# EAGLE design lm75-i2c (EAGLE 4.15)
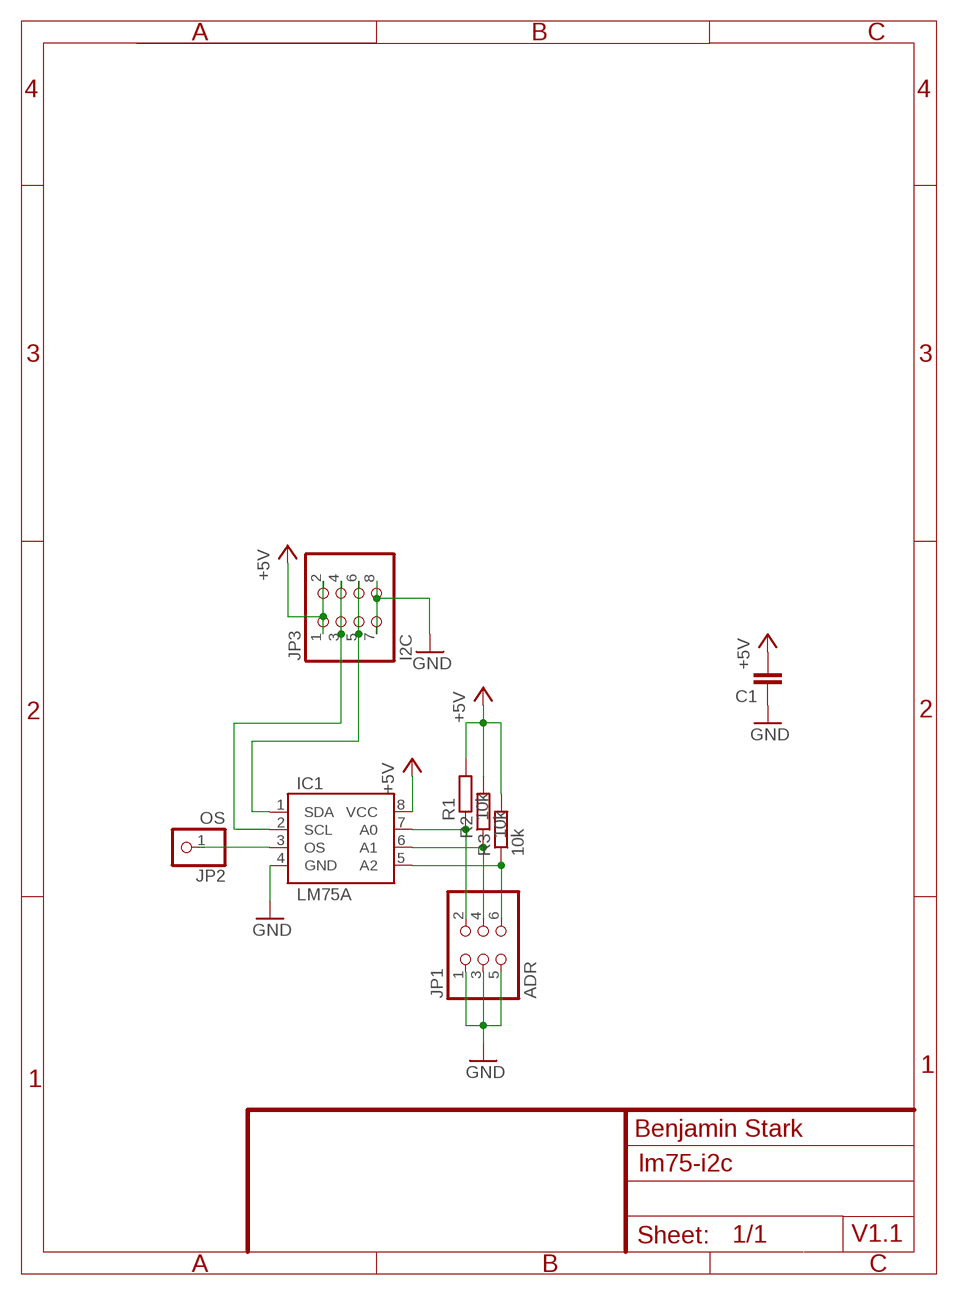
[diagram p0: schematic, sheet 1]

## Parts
C1  C-EU050-024X044  [C050-024X044]
IC1  LM75A  [SO8]
JP1  ADR  PINHD-2X3  [2X03]
JP2  OS  PINHD-1X1  [1X01]
JP3  I2C  PINHD-2X4  [2X04]
R1  10k  R-EU_0207/12  [0207/12]
R2  10k  R-EU_0207/12  [0207/12]
R3  10k  R-EU_0207/12  [0207/12]

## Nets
+5V: C1.2 IC1.8(VCC) JP3.1 JP3.2 R1.2 R2.2 R3.2
GND: C1.1 IC1.4(GND) JP1.1 JP1.3 JP1.5 JP3.7 JP3.8
N$1: IC1.3(OS) JP2.1
N$2: IC1.7(A0) JP1.2 R1.1
N$3: IC1.6(A1) JP1.4 R2.1
N$4: IC1.1(SDA) JP3.5 JP3.6
N$5: IC1.2(SCL) JP3.3 JP3.4
N$6: IC1.5(A2) JP1.6 R3.1

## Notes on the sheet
- Benjamin Stark
- V1.1

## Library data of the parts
C1 = rcl:C-EU: CAPACITOR, European symbol
IC1 = philips-3:LM75A
JP1 = pinhead:PINHD-2X3: PIN HEADER
JP2 = pinhead:PINHD-1X1: PIN HEADER
JP3 = pinhead:PINHD-2X4: PIN HEADER
R1-R3 = rcl:R-EU_: RESISTOR, European symbol

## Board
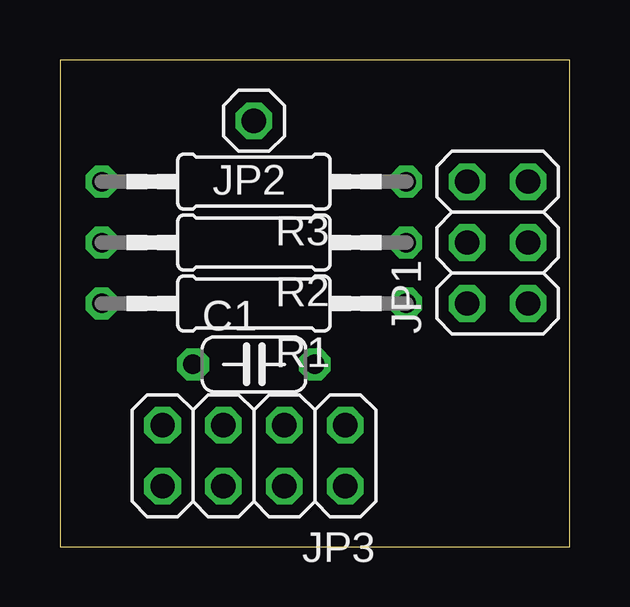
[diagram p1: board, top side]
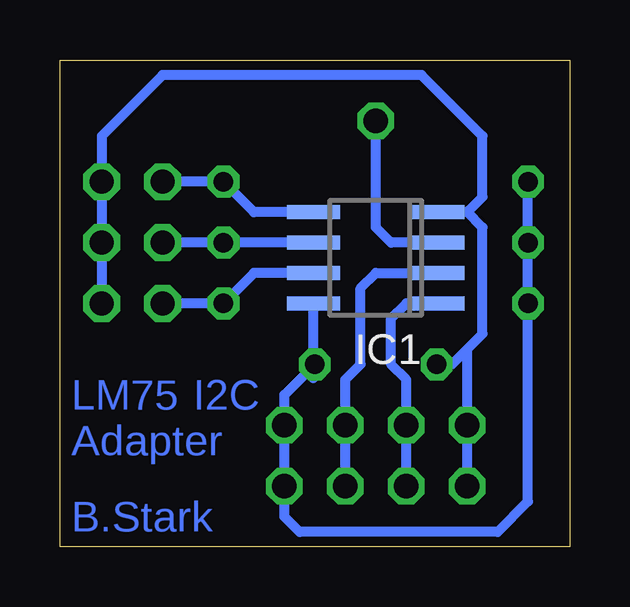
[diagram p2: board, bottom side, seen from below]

Size 21.26 x 20.31 mm. Coordinates in mm from the lower left corner, seen from the top.
Outline: 0,0 21.26,0 21.26,20.31 0,20.31 0,0
Copper layers (1*16): Top 0.035mm / dielectric 1.5mm / Bottom 0.035mm
Design rules "default": minimum track width 10mil, minimum drill 24mil, track to track 8mil, track to pad 8mil, pad to pad 8mil, via to via 8mil, smd to smd 8mil, copper to edge 40mil, drill to drill 8mil, minimum pad ring 10mil, minimum via ring 8mil, stop-mask expansion 4mil, vias tented up to drill 0mil, thermal gap 10mil

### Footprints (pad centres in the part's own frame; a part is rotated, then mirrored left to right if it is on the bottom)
C050-024X044 = drill 0.813 octagon: 1 -2.54,0; 2 2.54,0
SO8 = smd 0.6 x 2.2: 1 -1.905,-2.6; 2 -0.635,-2.6; 3 0.635,-2.6; 4 1.905,-2.6; 5 1.905,2.6; 6 0.635,2.6; 7 -0.635,2.6; 8 -1.905,2.6
2X03 = drill 1.016 octagon: 1 -2.54,-1.27; 2 -2.54,1.27; 3 0,-1.27; 4 0,1.27; 5 2.54,-1.27; 6 2.54,1.27
1X01 = drill 1.016 octagon: 1 0,0
2X04 = drill 1.016 octagon: 1 -3.81,-1.27; 2 -3.81,1.27; 3 -1.27,-1.27; 4 -1.27,1.27; 5 1.27,-1.27; 6 1.27,1.27; 7 3.81,-1.27; 8 3.81,1.27
0207/12 = drill 0.813 octagon: 1 -6.35,0; 2 6.35,0

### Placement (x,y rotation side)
C1  8.09,7.61 0 top
IC1  8.09,12.06 90 bottom
JP1  18.25,12.7 90 top
JP2  8.09,17.78 180 top
JP3  8.09,3.8 180 top
R1  8.09,10.15 180 top
R2  8.09,12.7 180 top
R3  8.09,15.24 180 top

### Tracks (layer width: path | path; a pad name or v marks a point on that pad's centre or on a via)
+5V
  Bottom 0.406: IC1.8 10.69,7.04 C1.2 11.9,6.34 JP3.1 JP3.2 11.9,1.27 11.26,0.63 3.01,0.63 1.74,1.9 R1.2 R2.2 R3.2
GND
  Bottom 0.406: 4.28,13.96 3.64,13.33 3.64,8.89 4.28,8.25 | 5.55,13.96 IC1.4 4.28,13.96 | JP1.1 JP1.3 JP1.5 19.52,17.14 16.98,19.68 6.18,19.68 3.64,17.14 3.64,14.6 4.28,13.96 | 4.28,8.25 JP3.7 JP3.8 | C1.1 4.91,7.61 4.28,8.25
N$1
  Bottom 0.406: IC1.3 7.45,12.7 8.09,13.33 JP2.1
N$2
  Bottom 0.406: IC1.7 13.17,11.43 R1.1 JP1.2
N$3
  Bottom 0.406: IC1.6 R2.1 JP1.4
N$4
  Bottom 0.406: IC1.1 6.82,10.15 7.45,9.52 7.45,7.61 6.82,6.98 JP3.5 JP3.6
N$5
  Bottom 0.406: IC1.2 8.09,11.43 8.72,10.79 8.72,7.61 9.36,6.98 JP3.3 JP3.4
N$6
  Bottom 0.406: IC1.5 13.17,13.96 R3.1 JP1.6

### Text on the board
Bottom: I2C | LM75 | Adapter | B.Stark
